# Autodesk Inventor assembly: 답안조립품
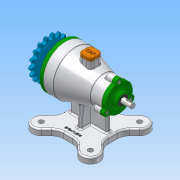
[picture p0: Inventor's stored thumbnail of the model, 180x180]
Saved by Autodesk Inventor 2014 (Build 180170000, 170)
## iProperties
Created: 2018-03
Part Number: 답안조립품
Document SubType Name: Assembly
Designer: 703
Author: 703
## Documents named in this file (15)
- C:\Users\user\Desktop\480307V1010\답안조립품.iam
- C:\Users\user\Desktop\480307V1010\본체.ipt
- C:\Users\user\Desktop\480307V1010\뒤커버.ipt
- C:\Users\user\Desktop\480307V1010\베어링-6200.ipt
- C:\Users\user\Desktop\480307V1010\볼트 M4 x 12.ipt
- 볼트 M4 x 12.ipt
- C:\Users\user\Desktop\480307V1010\오일 실 10 20 7.ipt
- C:\Users\user\Desktop\480307V1010\축.ipt
- C:\Users\user\Desktop\480307V1010\마개.ipt
- C:\Users\user\Desktop\480307V1010\베어링-6203.ipt
- C:\Users\user\Desktop\480307V1010\스프로킷.ipt
- C:\Users\user\Desktop\480307V1010\앞커버.ipt
- C:\Users\user\Desktop\480307V1010\오일 실 17 30 8.ipt
- C:\Users\user\Desktop\480307V1010\키 5 x 5.ipt
- 키 5 x 5.ipt
